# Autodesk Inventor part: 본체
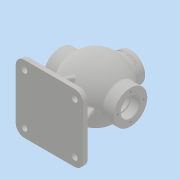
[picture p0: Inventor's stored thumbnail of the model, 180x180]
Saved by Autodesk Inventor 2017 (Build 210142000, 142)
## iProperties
Part Number: 본체
Material: 일반
Document SubType Name: Modeling
Designer: MRC
Density: 1 g/cm^3
Appearance: 기본값
Author: MRC
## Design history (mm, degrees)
sketch "스케치1"
  geometry: L1 (-65, 0)-(65, 0); L2 (-65, 0)-(-65, 31); L3 (-65, 31)-(-44.215, 31); L4 (65, 0)-(65, 31); L5 (65, 31)-(44.215, 31); A1 r 54 centre (0, 0) between (54, 0) and (-54, 0); A2 r 44 centre (0, 0) between (44, 0) and (-44, 0); 2 further points
  constraints: 10 end point, 6 point on circle, 6 point on line, 3 coincident, 2 centre point, 2 perpendicular, 1 horizontal, 1 midpoint, 1 vertical
  dimensions: "d0" = 130 distance of L1.start L1.end; "d1" = 108 diameter of A1; "d3" = 88 diameter of A2; "d15" = 62 diameter of L5 L1
node "작업 평면2"
sketch "스케치3"
  geometry: L1 (62.5, 62.5)-(-62.5, 62.5); L2 (-62.5, 62.5)-(-62.5, -62.5); L3 (-62.5, -62.5)-(62.5, -62.5); L4 (62.5, -62.5)-(62.5, 62.5); L5 (62.5, 62.5)-(-62.5, -62.5); L6 (-62.5, 62.5)-(62.5, -62.5); 1 further point
  constraints: 12 end point, 2 midpoint, 2 parallel, 1 horizontal, 1 perpendicular
  dimensions: "d10" = 125 distance of L3.end L2.end; "d11" = 125 distance of L2.end L1.end
extrude "돌출1" join sketch "스케치3" distance "d12" = 10; taper "d13" = 0 deg
revolve "회전2" stored, may be unused: angle "d16" = 90 deg
node "작업 평면3"
sketch "스케치4"
  geometry: C1 r 27 at (0, 0); 1 further point
  constraints: 1 centre point, 1 coincident
  dimensions: "d18" = 54 diameter of C1
extrude "돌출2" join sketch "스케치4" stored distance "d19" = 10; taper "d20" = 0 deg
sketch "스케치5"
  geometry: C1 r 31 at (0, 0) reference; C2 r 17.5 at (0, 0)
  constraints: 1 centre point, 1 coincident
  dimensions: "d21" = 35 diameter of C2
extrude "돌출3" cut sketch "스케치5" distance "d22" = 16; taper "d23" = 0 deg
sketch "스케치6"
  geometry: C1 r 31 at (0, 0) reference; C2 r 15 at (0, 0)
  constraints: 1 centre point, 1 coincident
  dimensions: "d24" = 30 diameter of C2
extrude "돌출4" cut sketch "스케치6" stored distance "d25" = 16; taper "d26" = 0 deg
sketch "스케치7"
  geometry: L1 (0, 0)-(0, 24); C1 r 31 at (0, 0) reference; 1 further point
  constraints: 2 end point, 1 coincident, 1 vertical
  dimensions: "d27" = 24 distance of L1.start L1.end
hole "구멍1" sketch "스케치7" at (0, 24) diameter "d28" = 3.242; stored, may be unused: countersink angle "d32" = 90 deg, drill point angle "d34" = 118 deg; dims "d29" = 12, "d30" = 4, "d31" = 2, "d33" = 15
chamfer "모따기1" distance "d38" = 1; stored, may be unused: second distance "d39" = 2, angle "d40" = 45 deg
fillet "모깎기1" dims "d41" = 0.6
sketch "스케치8"
  geometry: C1 r 27 at (0, 0) reference; C2 r 13 at (0, 0)
  constraints: 1 centre point, 1 coincident
  dimensions: "d42" = 26 diameter of C2
extrude "돌출5" cut sketch "스케치8" stored distance "d43" = 16; taper "d44" = 0 deg
chamfer "모따기2" distance "d45" = 1; stored, may be unused: second distance "d46" = 2, angle "d47" = 45 deg
sketch "스케치9"
  geometry: L1 (0, 0)-(0, 20); C1 r 14 at (0, 0) reference; 1 further point
  constraints: 2 end point, 1 coincident, 1 vertical
  dimensions: "d48" = 20 distance of L1.start L1.end
hole "구멍2" sketch "스케치9" at (0, 20) diameter "d49" = 3.242; stored, may be unused: countersink angle "d53" = 90 deg, drill point angle "d55" = 118 deg; dims "d50" = 9, "d51" = 4, "d52" = 2, "d54" = 11
fillet "모깎기4" dims "d73" = 16
sketch "스케치12"
  geometry: C1 r 5.5 at (46.5, -46.5); C2 r 5.5 at (-46.5, -46.5); C3 r 5.5 at (46.5, 46.5); C4 r 5.5 at (-46.5, 46.5); A1 r 16 centre (46.5, 46.5) between (62.5, 46.5) and (46.5, 62.5) reference; A2 r 16 centre (-46.5, 46.5) between (-46.5, 62.5) and (-62.5, 46.5) reference; A3 r 16 centre (-46.5, -46.5) between (-62.5, -46.5) and (-46.5, -62.5) reference; A4 r 16 centre (46.5, -46.5) between (46.5, -62.5) and (62.5, -46.5) reference; 1 further point
  constraints: 4 centre point, 4 coincident
  dimensions: "d74" = 11 diameter of C1; "d75" = 11 diameter of C2; "d76" = 11 diameter of C3; "d77" = 11 diameter of C4
extrude "돌출8" cut sketch "스케치12" stored distance "d78" = 8; taper "d79" = 0 deg
fillet "모깎기5" dims "d80" = 3
fillet "모깎기6" dims "d81" = 3
fillet "모깎기7" dims "d82" = 3
sketch "스케치13"
  geometry: L1 (-50.5, 4)-(50.5, 4); L2 (50.5, 4)-(50.5, -4); L3 (50.5, -4)-(-50.5, -4); L4 (-50.5, -4)-(-50.5, 4); L5 (-50.5, 4)-(50.5, -4); L6 (50.5, 4)-(-50.5, -4); L7 (4, 50.5)-(-4, 50.5); L8 (-4, 50.5)-(-4, -50.5); L9 (-4, -50.5)-(4, -50.5); L10 (4, -50.5)-(4, 50.5); L11 (4, 50.5)-(-4, -50.5); L12 (-4, 50.5)-(4, -50.5); 1 further point
  constraints: 24 end point, 4 midpoint, 4 parallel, 2 horizontal, 2 perpendicular
  dimensions: "d83" = 8 distance of L1.end L2.end; "d84" = 8 distance of L8.end L9.end; "d85" = 101 distance of L2.end L3.end; "d86" = 101 distance of L9.end L7.start
extrude "돌출9" join sketch "스케치13" stored distance "d87" = 8; taper "d88" = 0 deg
feature "면 기울기1" dims angle "d89" = 20 deg
fillet "모깎기8" dims "d90" = 3
fillet "모깎기9" dims "d91" = 3
node "작업 평면4"
sketch "스케치14"
  geometry: L1 (-27, 65)-(27, 65) reference; 2 further points
  constraints: 1 vertical alignment, 1 other
  dimensions: "d93" = 9 distance from line of L1 point (0, 56)
feature "엠보싱1" sketch "스케치14" dims "d0" = 130, "d1" = 108, "d3" = 88, "d15" = 62, "d94" = 0.5, "d95" = 0
chamfer "모따기3" distance "d102" = 1; stored, may be unused: second distance "d103" = 2, angle "d104" = 45 deg
fillet "모깎기10" dims "d105" = 0.6
node "솔리드1"
pattern_circular "원형 패턴3" dims angle "d97" = 360 deg
pattern_circular "원형 패턴4" dims angle "d100" = 360 deg
mirror "미러2"
mirror "미러3"
other parameters: "d9" = -85, "d17" = 65, "d92" = 131.5
